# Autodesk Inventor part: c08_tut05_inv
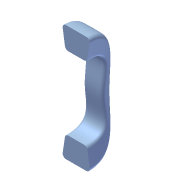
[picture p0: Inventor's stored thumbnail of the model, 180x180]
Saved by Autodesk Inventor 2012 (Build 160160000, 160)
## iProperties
Created: 2010-03
Part Number: c08_tut05_inv
Document SubType Name: Modeling
Designer: CADSoft
Density: 1 g/cm^3
Material: Default
Author: CADSoft
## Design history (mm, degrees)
sketch "Sketch1"
  geometry: L1 (30, 70)-(30, 60); L2 (20, 50)-(-20, 50); L3 (-30, 60)-(-30, 70); A1 r 45 centre (0, 36.459) between (30, 70) and (-30, 70); A2 r 10 centre (-20, 60) between (-30, 60) and (-20, 50); A3 r 10 centre (20, 60) between (20, 50) and (30, 60); 4 further points
  constraints: 6 end point, 6 point on circle, 4 point on line, 4 tangent, 3 centre point, 2 horizontal alignment, 1 coincident, 1 parallel, 1 other
  dimensions: "d4" = 60 distance of point (30, 50) point (-30, 50); "d5" = 30 distance from line of L1 point (0, 0); "d6" = 45 radius of A1; "d7" = 20 distance of point (-30, 50) L3.end; "d8" = 10 radius of A2; "d9" = 10 radius of A3; "d10" = 70 vertical distance of point (0, 0) L3.end
sketch "Sketch2"
  geometry: L1 (40.728, 163.479)-(33.805, 118.479); L2 (23.921, 110)-(-23.921, 110); L3 (-33.805, 118.479)-(-40.728, 163.479); L4 (-30.844, 175)-(30.844, 175); L5 (0, 187.351)-(0, 101.377); A1 r 10 centre (30.844, 165) between (40.728, 163.479) and (30.844, 175); A2 r 10 centre (-30.844, 165) between (-30.844, 175) and (-40.728, 163.479); A3 r 10 centre (-23.921, 120) between (-33.805, 118.479) and (-23.921, 110); A4 r 10 centre (23.921, 120) between (23.921, 110) and (33.805, 118.479); 5 further points
  constraints: 10 end point, 8 point on circle, 8 point on line, 8 tangent, 4 centre point, 3 equal radius, 1 horizontal, 1 parallel, 1 perpendicular
  dimensions: "d11" = 85 distance of point (-42.5, 175) point (42.5, 175); "d12" = 65 distance of point (32.5, 110) point (-32.5, 110); "d13" = 65 distance between parallel lines of L2 L4; "d14" = 175 distance from line of point (0, 0) L4; "d15" = 42.5 horizontal distance of point (0, 0) point (-42.5, 175); "d16" = 32.5 horizontal distance of point (0, 0) point (-32.5, 110); "d17" = 10 radius of A1
sketch "Sketch3"
  geometry: L1 (23.921, -110)-(-23.921, -110); L2 (-33.805, -118.479)-(-40.728, -163.479); L3 (-30.844, -175)-(30.844, -175); L4 (40.728, -163.479)-(33.805, -118.479); A1 r 10 centre (23.921, -120) between (33.805, -118.479) and (23.921, -110); A2 r 10 centre (-23.921, -120) between (-23.921, -110) and (-33.805, -118.479); A3 r 10 centre (-30.844, -165) between (-40.728, -163.479) and (-30.844, -175); A4 r 10 centre (30.844, -165) between (30.844, -175) and (40.728, -163.479); 5 further points
  constraints: 8 end point, 8 point on circle, 8 point on line, 8 tangent, 4 centre point, 3 equal radius, 1 horizontal, 1 parallel
  dimensions: "d18" = 65 distance between parallel lines of L3 L1; "d19" = 65 distance of point (32.5, -110) point (-32.5, -110); "d20" = 85 distance of point (-42.5, -175) point (42.5, -175); "d21" = 32.5 horizontal distance of point (0, 0) point (-32.5, -110); "d22" = 42.5 horizontal distance of point (0, 0) point (-42.5, -175); "d23" = 175 distance from line of point (0, 0) L3; "d24" = 10 radius of A1
loft "Loft1" sketch "Sketch1", "Sketch2", "Sketch3" dims "d25" = 500, "d26" = 90 deg, "d27" = 0, "d28" = 90 deg, "d29" = 500, "d30" = 90 deg
body "Solid1"
